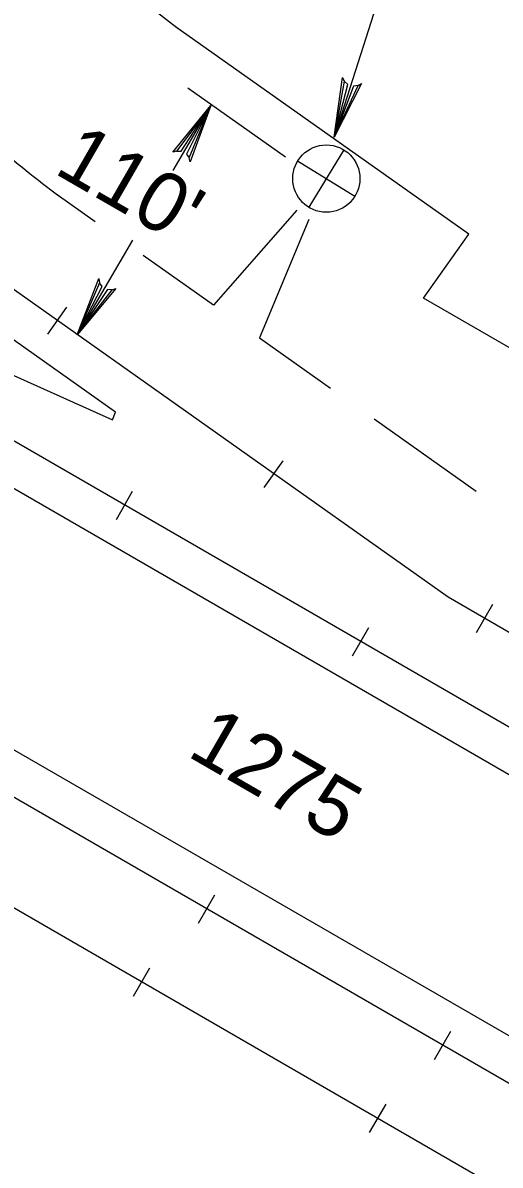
# Model space of a CAD drawing. Extents: x 36 to 2622, y -5330 to 219.
# Drawn here: x 593.7 to 617.9, y -5107 to -5049.2 of the extents above; entities that cross this region are included whole.
import ezdxf

# ---------------------------------------------------------------- set-up
doc = ezdxf.new("R2010")
doc.units = 0
doc.layers.add('2', color=7, linetype='Continuous')
doc.layers.add('3', color=7, linetype='Continuous')

# ---------------------------------------------------------------- blocks, each defined once
blk = doc.blocks.new('RARROW')
at = {"layer": '3'}
blk.add_lwpolyline([(-2.2695, 0.285), (-2.184875, 0.12075), (0, 0), (-2.2695, 0.285), (-2.38575, 0.384625), (0, 0), (-2.183125, -0.108), (-2.262875, -0.2705), (0, 0), (-2.38575, -0.379125), (-2.262875, -0.2705)], dxfattribs=at)

msp = doc.modelspace()

# ---------------------------------------------------------------- linework, layer by layer
at = {"layer": '2'}
for p, q in [((699.623, -5134.156), (428.193, -4977.446)), ((700.667, -5132.348), (434.985, -4978.962)), ((693.9, -5144.068), (416.962, -4984.173)), ((692.86, -5145.872), (414.78, -4985.319)), ((613.229, -5043.207), (609.487, -5054.948)), ((616.304, -5059.868), (601.457, -5049.365)), ((607.018, -5055.969), (602.077, -5052.475)), ((603.234, -5053.355), (601.318, -5056.641)), ((609.974, -5055.597), (608.195, -5058.499)), ((607.636, -5056.159), (610.538, -5057.937)), ((595.45, -5057.856), (597.376, -5059.219)), ((607.6, -5058.647), (603.373, -5063.462)), ((608.21, -5059.117), (605.701, -5065.108)), ((599.267, -5060.161), (596.475, -5064.954)), ((614.012, -5063.109), (616.304, -5059.868)), ((603.373, -5063.462), (599.818, -5060.947)), ((615.251, -5078.236), (592.446, -5062.102)), ((661.896, -5090.759), (614.012, -5063.109)), ((586.158, -5063.841), (598.26, -5069.26)), ((598.414, -5068.875), (591.244, -5063.801)), ((594.982, -5064.916), (595.941, -5063.562)), ((605.701, -5065.108), (609.304, -5067.656)), ((598.26, -5069.26), (598.414, -5068.875)), ((611.503, -5069.214), (616.676, -5072.873)), ((605.945, -5072.682), (606.904, -5071.328)), ((598.454, -5074.298), (599.279, -5072.865)), ((702.741, -5128.756), (615.251, -5078.236)), ((616.695, -5080.029), (617.527, -5078.594)), ((610.417, -5081.204), (611.243, -5079.771)), ((690.43, -5150.076), (590.632, -5092.448)), ((602.61, -5094.728), (603.436, -5093.294)), ((599.321, -5098.426), (600.151, -5096.989)), ((614.571, -5101.634), (615.397, -5100.201)), ((611.28, -5105.335), (612.11, -5103.897))]:
    msp.add_line(p, q, dxfattribs=at)
msp.add_circle((609.087, -5057.05), 1.702, dxfattribs=at)
for radius, start, end in [(39.587, 206.82274, 233.40034), (49.988, 228.59706, 233.39953)]:
    msp.add_arc((625.352, -5017.796), radius, start, end, dxfattribs=at)

# ---------------------------------------------------------------- block references
at = {"layer": '2', "xscale": 1.2574347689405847, "yscale": 1.3092961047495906}
for p, rotation in [((609.487, -5054.948), -107.38872915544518), ((603.234, -5053.354), 60.48829894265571), ((596.475, -5064.954), -120.34231276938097)]:
    msp.add_blockref('RARROW', p, dxfattribs=dict(at, rotation=rotation))

# ---------------------------------------------------------------- texts
at = {"layer": '2'}
for s, p in [("110'", (595.229, -5056.737)), ('1275', (601.969, -5086.234))]:
    msp.add_text(s, height=2.9955, rotation=330, dxfattribs=at).set_placement(p)

doc.saveas('drawing.dxf')
